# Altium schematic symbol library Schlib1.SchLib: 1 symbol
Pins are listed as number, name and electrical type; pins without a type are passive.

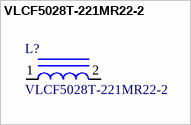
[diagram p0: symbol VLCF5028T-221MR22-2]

## VLCF5028T-221MR22-2
designator L?
INDUCTOR POWER 220UH .22A SMD; Manufacturer: TDK Corporation; Area: 28000
footprint SMD (Footprint not found)
footprint IND_500X500_280 (INDUCTOR POWER 220UH .22A SMD)
footprint IND_500X500_280 (INDUCTOR POWER 220UH .22A SMD)
pins: 1, 2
